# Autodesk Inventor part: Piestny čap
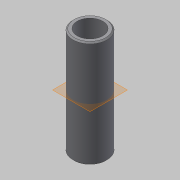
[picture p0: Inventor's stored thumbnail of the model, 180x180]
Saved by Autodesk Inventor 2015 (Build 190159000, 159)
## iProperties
Created: 2012-10
Part Number: Piestny čap
Document SubType Name: Modeling
Designer: Michman
Material: Všeobecné
Density: 1 g/cm^3
Mass: 0.547573 g
Surface Area: 11.3447 cm^2
Volume: 0.547573 cm^3
Appearance: Výchozí
Author: Michman
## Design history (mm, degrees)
sketch "Náčrt1"
  geometry: C1 r 4 at (0, 0); C2 r 3 at (0, 0)
  constraints: 2 centre point, 1 coincident
  dimensions: "d0" = 8 diameter of C1; "d1" = 6 diameter of C2
extrude "Vysunutí1" new body sketch "Náčrt1" distance "d2" = 25; taper "d3" = 0 deg
chamfer "Zkosení1" distance "d4" = 0.3; stored, may be unused: second distance "d5" = 2, angle "d6" = 45 deg
node "Pracovní rovina1"
node "Těleso1"
node "Objemová tělesa"
node "Povrchová tělesa"
